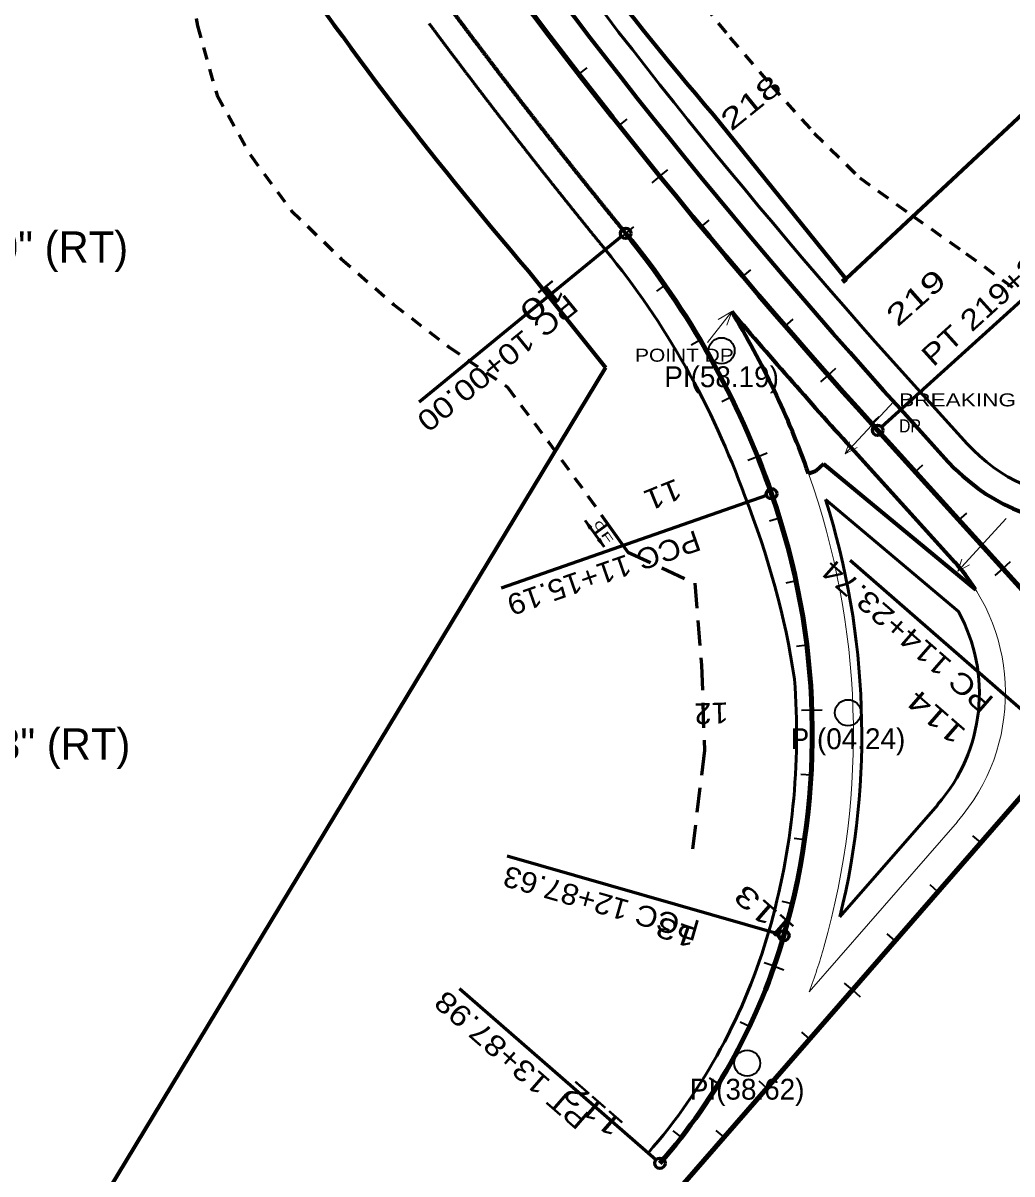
# Model space of a CAD drawing. Extents: x 2717836 to 2719883, y 337327 to 339813.
# Drawn here: x 2718674.4 to 2719054.1, y 337871.3 to 338313.3 of the extents above; entities that cross this region are included whole.
import ezdxf
from ezdxf.enums import TextEntityAlignment as Align

# ---------------------------------------------------------------- set-up
doc = ezdxf.new("R2010")
doc.units = 0
doc.header["$LTSCALE"] = 3.2
for name, pattern in [('LONG_DASHED', [7.5, 6, -1.5]), ('MEDIUM_DASHED', [4.5, 3, -1.5]), ('SHORT_DASHED', [2.7, 1.5, -1.2])]:
    doc.linetypes.add(name, pattern=pattern)
for name, color, linetype, lineweight in [('1', 7, 'Continuous', 106), ('2', 7, 'Continuous', 13), ('22', 7, 'SHORT_DASHED', 60), ('23', 7, 'Continuous', 70), ('3', 7, 'Continuous', 70), ('31', 7, 'Continuous', 35), ('52', 7, 'Continuous', 53), ('6', 7, 'Continuous', 53), ('60', 7, 'Continuous', 13), ('61', 7, 'Continuous', 13), ('62', 7, 'Continuous', 13), ('8', 7, 'Continuous', 70)]:
    doc.layers.add(name, color=color, linetype=linetype, lineweight=lineweight)

msp = doc.modelspace()

# ---------------------------------------------------------------- hatches: boundary and pattern name
at = {"layer": '23'}
msp.add_hatch(color=256, dxfattribs=at).paths.add_polyline_path([(2718989.701, 338213.433), (2718988.659, 338214.512), (2718989.738, 338215.554), (2718990.78, 338214.474)])
at = {"layer": '52'}
for points in [[(2718890.257, 338122.283), (2718892.832, 338119.693), (2718891.815, 338120.076), (2718891.826, 338118.982)], [(2718897.478, 338112.08), (2718894.903, 338114.67), (2718895.92, 338114.288), (2718895.908, 338115.382)]]:
    msp.add_hatch(color=256, dxfattribs=at).paths.add_polyline_path(points)

# ---------------------------------------------------------------- linework, layer by layer
at = {"layer": '1'}
for p, q in [((2719002.473, 338156.897), (2719189.327, 337950.539)), ((2718598.813, 337489.479), (2719074.059, 338035.314))]:
    msp.add_line(p, q, dxfattribs=at)
for centre, radius, start, end in [((2720744.453, 339734.238), 2350, 206.79977, 222.16044), ((2718650.191, 338023.775), 330, 19.23982, 39.23982), ((2718697.399, 338040.251), 280, 343.95467, 19.23982), ((2718745.451, 338026.431), 230, 318.95467, 343.95467)]:
    msp.add_arc(centre, radius, start, end, dxfattribs=at)
at = {"layer": '2'}
msp.add_line((2719033.086, 338006.53), (2718976.223, 337941.221), dxfattribs=at)
for centre, radius, start, end in [((2718692.921, 338040.106), 300.266, 344.21749, 19.50264), ((2718976.549, 338055.909), 75, 318.86607, 42.16044), ((2718745.451, 338026.431), 246, 339.73408, 343.95467)]:
    msp.add_arc(centre, radius, start, end, dxfattribs=at)
at = {"layer": '22'}
for p, q in [((2718736.378, 338340.568), (2718741.398, 338312.243)), ((2718930.49, 338326.699), (2718945.807, 338307.673)), ((2718741.398, 338312.243), (2718748.912, 338285.405)), ((2718945.807, 338307.673), (2718961.775, 338289.179)), ((2718961.775, 338289.179), (2718978.102, 338271.004)), ((2718748.912, 338285.405), (2718761.889, 338262.366)), ((2718978.102, 338271.004), (2718995.614, 338253.858)), ((2718761.889, 338262.366), (2718777.485, 338241.226)), ((2718995.614, 338253.858), (2719015.923, 338239.196)), ((2718777.485, 338241.226), (2718796.55, 338222.768)), ((2718796.55, 338222.768), (2718816.646, 338205.231)), ((2718816.646, 338205.231), (2718837.975, 338188.825)), ((2718837.975, 338188.825), (2718860.375, 338173.479)), ((2718860.375, 338173.479), (2718875.971, 338152.581)), ((2718875.971, 338152.581), (2718891.404, 338131.497)), ((2718891.404, 338131.497), (2718898.972, 338120.794))]:
    msp.add_line(p, q, dxfattribs=at)
at = {"layer": '22', "linetype": 'LONG_DASHED'}
msp.add_line((2718898.972, 338120.794), (2718906.541, 338110.092), dxfattribs=at)
at = {"layer": '22', "linetype": 'MEDIUM_DASHED'}
msp.add_line((2718906.541, 338110.092), (2718932.305, 338098.2), dxfattribs=at)
at = {"layer": '22'}
msp.add_lwpolyline([(2719015.923, 338239.196), (2719036.374, 338224.824), (2719056.377, 338210.214)], dxfattribs=at)
at = {"layer": '22', "linetype": 'MEDIUM_DASHED'}
msp.add_lwpolyline([(2718932.305, 338098.2), (2718934.904, 338066.645), (2718935.99, 338033.903), (2718931.4, 337996.021)], dxfattribs=at)
at = {"layer": '23'}
for p, q in [((2719374.169, 338574.501), (2718990.259, 338215.014)), ((2718939.297, 338278.13), (2718990.259, 338215.014)), ((2718868.503, 338217.98), (2718898.006, 338180.983)), ((2718898.006, 338180.983), (2718492.996, 337510.896))]:
    msp.add_line(p, q, dxfattribs=at)
at = {"layer": '23', "lineweight": 25}
msp.add_lwpolyline([(2718989.701, 338213.433), (2718988.659, 338214.512), (2718989.738, 338215.554), (2718990.78, 338214.474)], close=True, dxfattribs=at)
at = {"layer": '23'}
for centre, radius, start, end in [((2718932.366, 337992.345), 585.751, 113.27176, 113.27176), ((2720030.046, 339206.574), 1432.39, 206.96023, 220.40436), ((2719954.557, 339151.911), 1432.39, 206.65897, 220.69325)]:
    msp.add_arc(centre, radius, start, end, dxfattribs=at)
at = {"layer": '3'}
for p, q in [((2719011.368, 338164.951), (2719029.47, 338144.96)), ((2718975.96, 338140.349), (2718978.769, 338141.359)), ((2718981.734, 338144.044), (2718978.769, 338141.359))]:
    msp.add_line(p, q, dxfattribs=at)
at = {"layer": '3', "lineweight": 13}
msp.add_lwpolyline([(2718993.577, 338148.842), (2719031.255, 338107.232), (2719032.145, 338106.25)], dxfattribs=at)
at = {"layer": '3'}
msp.add_lwpolyline([(2718981.734, 338144.044), (2719039.155, 338096.513), (2719040.109, 338095.724)], dxfattribs=at)
for centre, radius, start, end in [((2720744.453, 339734.238), 2338, 206.79977, 222.16044), ((2718650.191, 338023.775), 330, 19.23982, 39.23982), ((2718650.191, 338023.775), 330, 19.23982, 39.23982), ((2719085.065, 338195.301), 75, 222.16044, 316.72468), ((2718697.399, 338040.251), 280, 343.95467, 19.23982), ((2718697.399, 338040.251), 280, 343.95467, 19.23982), ((2718745.451, 338026.431), 230, 318.95467, 343.95467), ((2718745.451, 338026.431), 230, 318.95467, 343.95467)]:
    msp.add_arc(centre, radius, start, end, dxfattribs=at)
at = {"layer": '3', "lineweight": 13}
for centre, radius, start, end in [((2718662.067, 338029.421), 332.917, 19.82595, 31.31675), ((2720759.569, 339747.514), 2382.117, 220.43651, 222.14825), ((2721152.646, 340103.725), 2912.583, 222.15462, 222.1586), ((2718640.384, 338021.681), 355.94, 19.4749, 19.81422)]:
    msp.add_arc(centre, radius, start, end, dxfattribs=at)
at = {"layer": '3'}
for points in [[(2718838.33, 338319.116), (2718838.769, 338318.524), (2718839.215, 338317.924), (2718839.655, 338317.332), (2718840.102, 338316.732), (2718840.542, 338316.141), (2718840.989, 338315.541), (2718841.429, 338314.95), (2718841.87, 338314.359), (2718842.318, 338313.76), (2718842.759, 338313.169), (2718843.207, 338312.57), (2718843.648, 338311.98), (2718844.09, 338311.39), (2718844.538, 338310.791), (2718844.981, 338310.201), (2718845.429, 338309.603), (2718845.872, 338309.013), (2718846.321, 338308.415), (2718846.764, 338307.826), (2718847.207, 338307.236), (2718847.656, 338306.639), (2718848.1, 338306.05), (2718848.55, 338305.453), (2718848.994, 338304.864), (2718849.438, 338304.275), (2718849.888, 338303.679), (2718850.333, 338303.09), (2718850.783, 338302.494), (2718851.228, 338301.906), (2718851.679, 338301.309), (2718852.124, 338300.722), (2718852.57, 338300.134), (2718853.022, 338299.538), (2718853.467, 338298.951), (2718853.919, 338298.355), (2718854.365, 338297.768), (2718854.818, 338297.173), (2718855.264, 338296.586), (2718855.711, 338295.999), (2718856.164, 338295.405), (2718856.611, 338294.818), (2718857.064, 338294.224), (2718857.512, 338293.637), (2718857.96, 338293.051), (2718858.413, 338292.457), (2718858.861, 338291.872), (2718859.316, 338291.278), (2718859.764, 338290.692), (2718860.219, 338290.099), (2718860.667, 338289.514), (2718861.116, 338288.929), (2718861.571, 338288.336), (2718862.021, 338287.751), (2718862.476, 338287.158), (2718862.926, 338286.574), (2718863.376, 338285.989), (2718863.832, 338285.397), (2718864.282, 338284.813), (2718864.738, 338284.221), (2718865.189, 338283.637), (2718865.646, 338283.045), (2718866.097, 338282.462), (2718866.548, 338281.878), (2718867.005, 338281.287), (2718867.457, 338280.704), (2718867.914, 338280.113), (2718868.366, 338279.53), (2718868.818, 338278.947), (2718869.277, 338278.357), (2718869.729, 338277.774), (2718870.188, 338277.184), (2718870.64, 338276.602), (2718871.099, 338276.012), (2718871.553, 338275.43)], [(2718871.553, 338275.43), (2718872.006, 338274.848), (2718872.465, 338274.259), (2718872.919, 338273.677), (2718873.379, 338273.088), (2718873.833, 338272.507), (2718874.293, 338271.918), (2718874.748, 338271.337), (2718875.202, 338270.756), (2718875.663, 338270.168), (2718876.118, 338269.587), (2718876.579, 338268.999), (2718877.035, 338268.419), (2718877.49, 338267.839), (2718877.952, 338267.251), (2718878.408, 338266.671), (2718878.87, 338266.084), (2718879.326, 338265.504), (2718879.789, 338264.917), (2718880.245, 338264.338), (2718880.702, 338263.759), (2718881.165, 338263.172), (2718881.622, 338262.593), (2718882.086, 338262.007), (2718882.543, 338261.428), (2718883.001, 338260.85), (2718883.465, 338260.264), (2718883.923, 338259.686), (2718884.387, 338259.1), (2718884.845, 338258.522), (2718885.31, 338257.937), (2718885.769, 338257.36), (2718886.228, 338256.782), (2718886.693, 338256.197), (2718887.152, 338255.62), (2718887.618, 338255.035), (2718888.078, 338254.459), (2718888.537, 338253.882), (2718889.004, 338253.298), (2718889.464, 338252.721), (2718889.93, 338252.137), (2718890.391, 338251.561), (2718890.858, 338250.978), (2718891.319, 338250.402), (2718891.78, 338249.826), (2718892.247, 338249.243), (2718892.709, 338248.668), (2718893.176, 338248.085), (2718893.638, 338247.51), (2718894.106, 338246.927), (2718894.569, 338246.352), (2718895.031, 338245.778), (2718895.5, 338245.195), (2718895.962, 338244.621), (2718896.431, 338244.039), (2718896.894, 338243.465), (2718897.358, 338242.891), (2718897.827, 338242.31), (2718898.291, 338241.736), (2718898.761, 338241.155), (2718899.225, 338240.581), (2718899.695, 338240), (2718900.16, 338239.427), (2718900.624, 338238.855), (2718901.095, 338238.274), (2718901.56, 338237.702), (2718902.031, 338237.121), (2718902.496, 338236.549), (2718902.962, 338235.977), (2718903.433, 338235.397), (2718903.899, 338234.825), (2718904.371, 338234.246), (2718904.837, 338233.674), (2718905.776, 338232.524)]]:
    msp.add_spline(points, degree=3, dxfattribs=at)
at = {"layer": '31'}
for p, q in [((2718887.829, 338293.596), (2718890.989, 338296.049)), ((2718903.26, 338273.927), (2718906.394, 338276.413)), ((2718918.899, 338254.423), (2718922.006, 338256.942)), ((2718918.899, 338254.423), (2718915.792, 338251.904)), ((2718905.778, 338232.522), (2718908.876, 338235.052)), ((2718934.745, 338235.086), (2718937.825, 338237.638)), ((2718905.778, 338232.522), (2718902.68, 338229.992)), ((2718950.795, 338215.919), (2718953.848, 338218.503)), ((2718920.844, 338212.579), (2718917.563, 338210.291)), ((2718967.049, 338196.924), (2718970.074, 338199.541)), ((2718934.357, 338191.553), (2718930.913, 338189.52)), ((2718983.503, 338178.103), (2718986.501, 338180.751)), ((2718983.503, 338178.103), (2718980.506, 338175.454)), ((2718946.241, 338169.565), (2718942.652, 338167.798)), ((2719000.157, 338159.458), (2719003.126, 338162.138)), ((2718956.426, 338146.74), (2718952.714, 338145.25)), ((2718956.426, 338146.74), (2718960.137, 338148.231)), ((2719016.936, 338140.924), (2719019.901, 338143.609)), ((2718964.829, 338123.202), (2718961.009, 338122.017)), ((2719033.716, 338122.392), (2719036.681, 338125.077)), ((2719050.496, 338103.861), (2719053.461, 338106.546)), ((2719050.496, 338103.861), (2719047.531, 338101.176)), ((2718971.16, 338099.026), (2718967.249, 338098.186)), ((2718975.311, 338074.381), (2718971.34, 338073.893)), ((2718977.247, 338049.464), (2718973.249, 338049.333)), ((2718977.247, 338049.464), (2718981.245, 338049.596)), ((2718976.954, 338024.474), (2718972.96, 338024.7)), ((2718974.433, 337999.61), (2718970.476, 338000.191)), ((2719042.056, 337998.557), (2719039.039, 338001.184)), ((2719025.639, 337979.703), (2719022.623, 337982.329)), ((2718969.706, 337975.07), (2718965.816, 337976.001)), ((2719009.223, 337960.848), (2719006.206, 337963.475)), ((2718962.753, 337951.067), (2718958.974, 337952.377)), ((2718962.753, 337951.067), (2718966.532, 337949.756)), ((2718992.807, 337941.993), (2718989.79, 337944.62)), ((2718992.807, 337941.993), (2718995.823, 337939.367)), ((2718953.295, 337927.938), (2718949.68, 337929.651)), ((2718976.39, 337923.138), (2718973.373, 337925.765)), ((2718941.384, 337905.972), (2718937.976, 337908.067)), ((2718959.974, 337904.284), (2718956.957, 337906.91)), ((2718927.16, 337885.428), (2718923.999, 337887.88)), ((2718943.557, 337885.429), (2718940.541, 337888.056))]:
    msp.add_line(p, q, dxfattribs=at)
at = {"layer": '31', "lineweight": 60}
for p, q in [((2718904.229, 338231.257), (2718826.462, 338167.741)), ((2719003.955, 338158.239), (2719083.848, 338230.581)), ((2718959.872, 338131.858), (2718857.934, 338096.28)), ((2719072.55, 338036.627), (2718991.882, 338106.863)), ((2718964.569, 337963.412), (2718860.262, 337993.411)), ((2718917.406, 337876.713), (2718842.011, 337942.358))]:
    msp.add_line(p, q, dxfattribs=at)
for centre in [(2718905.778, 338232.522), (2719002.473, 338156.897), (2718961.76, 338132.517), (2718966.491, 337962.86), (2718918.914, 337875.4)]:
    msp.add_circle(centre, 2, dxfattribs=at)
at = {"layer": '31'}
for centre in [(2718942.586, 338187.455), (2718991.104, 338048.441), (2718952.397, 337913.856)]:
    msp.add_circle(centre, 5, dxfattribs=at)
at = {"layer": '52'}
for p, q in [((2718890.257, 338122.283), (2718897.478, 338112.08)), ((2718893.867, 338117.182), (2718898.972, 338120.794))]:
    msp.add_line(p, q, dxfattribs=at)
at = {"layer": '52', "lineweight": 25}
for points in [[(2718890.257, 338122.283), (2718892.832, 338119.693), (2718891.815, 338120.076), (2718891.826, 338118.982)], [(2718897.478, 338112.08), (2718894.903, 338114.67), (2718895.92, 338114.288), (2718895.908, 338115.382)]]:
    msp.add_lwpolyline(points, close=True, dxfattribs=at)
at = {"layer": '6'}
for p, q in [((2719018.781, 338171.663), (2719036.882, 338151.672)), ((2718982.514, 338130.307), (2719033.495, 338087.249)), ((2718988.031, 337970.012), (2719025.544, 338013.097))]:
    msp.add_line(p, q, dxfattribs=at)
for centre, radius, start, end in [((2720744.453, 339734.238), 2328, 208.64257, 222.16044), ((2718650.191, 338023.775), 320, 19.68984, 39.23982), ((2719085.065, 338195.301), 65, 222.16044, 316.72468), ((2718654.256, 338013.029), 320, 8.68814, 21.747), ((2718697.399, 338040.251), 299, 346.41349, 17.52915), ((2718976.549, 338055.909), 65, 318.86607, 28.82624), ((2718697.399, 338040.251), 274, 343.95467, 4.41993), ((2718745.451, 338026.431), 224, 318.95467, 343.95467)]:
    msp.add_arc(centre, radius, start, end, dxfattribs=at)
for points in [[(2718830.301, 338313.154), (2718830.742, 338312.56), (2718831.19, 338311.958), (2718831.632, 338311.364), (2718832.08, 338310.761), (2718832.522, 338310.167), (2718832.971, 338309.565), (2718833.413, 338308.972), (2718833.856, 338308.378), (2718834.305, 338307.777), (2718834.748, 338307.183), (2718835.198, 338306.582), (2718835.641, 338305.989), (2718836.085, 338305.396), (2718836.535, 338304.795), (2718836.979, 338304.203), (2718837.43, 338303.602), (2718837.874, 338303.01), (2718838.325, 338302.409), (2718838.77, 338301.817), (2718839.215, 338301.225), (2718839.666, 338300.626), (2718840.112, 338300.034), (2718840.564, 338299.434), (2718841.009, 338298.843), (2718841.455, 338298.252), (2718841.908, 338297.653), (2718842.354, 338297.062), (2718842.807, 338296.463), (2718843.253, 338295.872), (2718843.706, 338295.274), (2718844.153, 338294.683), (2718844.601, 338294.093), (2718845.054, 338293.495), (2718845.502, 338292.905), (2718845.956, 338292.307), (2718846.404, 338291.717), (2718846.858, 338291.12), (2718847.307, 338290.53), (2718847.755, 338289.941), (2718848.21, 338289.344), (2718848.659, 338288.755), (2718849.114, 338288.158), (2718849.564, 338287.569), (2718850.013, 338286.981), (2718850.469, 338286.384), (2718850.919, 338285.796), (2718851.375, 338285.2), (2718851.825, 338284.612), (2718852.282, 338284.016), (2718852.732, 338283.428), (2718853.183, 338282.84), (2718853.64, 338282.245), (2718854.091, 338281.658), (2718854.549, 338281.063), (2718855, 338280.476), (2718855.452, 338279.889), (2718855.91, 338279.294), (2718856.362, 338278.707), (2718856.821, 338278.113), (2718857.273, 338277.527), (2718857.732, 338276.932), (2718858.185, 338276.346), (2718858.638, 338275.76), (2718859.097, 338275.167), (2718859.55, 338274.581), (2718860.01, 338273.988), (2718860.464, 338273.402), (2718860.918, 338272.817), (2718861.378, 338272.224), (2718861.832, 338271.639), (2718862.293, 338271.046), (2718862.747, 338270.462), (2718863.208, 338269.869), (2718863.662, 338269.286)], [(2718863.664, 338269.284), (2718864.119, 338268.701), (2718864.58, 338268.109), (2718865.036, 338267.525), (2718865.498, 338266.933), (2718865.953, 338266.35), (2718866.416, 338265.758), (2718866.872, 338265.175), (2718867.328, 338264.592), (2718867.791, 338264.001), (2718868.248, 338263.418), (2718868.711, 338262.827), (2718869.169, 338262.244), (2718869.626, 338261.662), (2718870.09, 338261.072), (2718870.547, 338260.49), (2718871.012, 338259.9), (2718871.47, 338259.318), (2718871.934, 338258.728), (2718872.393, 338258.146), (2718872.851, 338257.565), (2718873.316, 338256.976), (2718873.775, 338256.394), (2718874.241, 338255.805), (2718874.7, 338255.224), (2718875.16, 338254.644), (2718875.626, 338254.055), (2718876.086, 338253.475), (2718876.552, 338252.886), (2718877.012, 338252.306), (2718877.479, 338251.718), (2718877.94, 338251.138), (2718878.4, 338250.559), (2718878.868, 338249.971), (2718879.329, 338249.392), (2718879.796, 338248.804), (2718880.258, 338248.225), (2718880.72, 338247.646), (2718881.188, 338247.059), (2718881.65, 338246.481), (2718882.119, 338245.894), (2718882.581, 338245.316), (2718883.05, 338244.73), (2718883.513, 338244.151), (2718883.976, 338243.573), (2718884.445, 338242.988), (2718884.909, 338242.41), (2718885.378, 338241.824), (2718885.842, 338241.247), (2718886.312, 338240.662), (2718886.776, 338240.085), (2718887.241, 338239.508), (2718887.711, 338238.923), (2718888.176, 338238.346), (2718888.647, 338237.762), (2718889.112, 338237.185), (2718889.577, 338236.609), (2718890.049, 338236.025), (2718890.514, 338235.449), (2718890.986, 338234.865), (2718891.452, 338234.29), (2718891.925, 338233.706), (2718892.391, 338233.131), (2718892.857, 338232.556), (2718893.33, 338231.973), (2718893.797, 338231.398), (2718894.27, 338230.815), (2718894.737, 338230.24), (2718895.205, 338229.666), (2718895.679, 338229.084), (2718896.146, 338228.509), (2718896.62, 338227.927), (2718897.089, 338227.353), (2718898.029, 338226.201)]]:
    msp.add_spline(points, degree=3, dxfattribs=at)
at = {"layer": '60'}
msp.add_line((2719033.232, 338102.845), (2719034.862, 338107.376), dxfattribs=at)
msp.add_lwpolyline([(2719051.887, 338122.962), (2719033.232, 338102.845), (2719037.76, 338105.201)], dxfattribs=at)
at = {"layer": '61'}
msp.add_line((2718990.042, 338147.876), (2718994.569, 338150.232), dxfattribs=at)
msp.add_lwpolyline([(2719008.697, 338167.993), (2718990.042, 338147.876), (2718991.672, 338152.407)], dxfattribs=at)
at = {"layer": '62'}
for p in [(2718937.158, 338190.612), (2718941.324, 338199.492), (2718944.584, 338197.317)]:
    msp.add_line(p, (2718946.477, 338202.464), dxfattribs=at)
at = {"layer": '8'}
for p, q in [((2718993.575, 338148.843), (2719032.142, 338106.25)), ((2718975.957, 338140.35), (2718978.767, 338141.36)), ((2718981.732, 338144.045), (2718978.767, 338141.36)), ((2718981.732, 338144.045), (2719040.053, 338095.769))]:
    msp.add_line(p, q, dxfattribs=at)
for centre, radius, start, end in [((2720744.451, 339734.239), 2362, 220.42917, 222.16044), ((2718650.189, 338023.776), 346, 19.68926, 31.09375), ((2718976.547, 338055.91), 75, 32.50196, 42.16044)]:
    msp.add_arc(centre, radius, start, end, dxfattribs=at)

# ---------------------------------------------------------------- texts
at = {"layer": '31'}
for s, rotation, width, p in [('218', 39.029, 1.45, (2718946.276, 338271.466)), ('PT 219+28.45', 42.16, 1.2, (2719023.844, 338180.97)), ('219', 41.467, 1.45, (2719010.131, 338196.295)), ('10', 219.24, 1.55, (2718878.463, 338215.378)), ('PC 10+00.00', 219.24, 1.2, (2718883.208, 338209.569)), ('11', 201.877, 1.2, (2718925.24, 338138.528)), ('PCC 11+15.19', 199.24, 1.1, (2718932.701, 338118.668)), ('PC 114+23.74', 138.955, 1.2, (2719047.626, 338053.687)), ('114', 138.955, 1.4, (2719036.965, 338041.442)), ('12', 181.886, 1.1, (2718945.133, 338052.409)), ('PCC 12+87.63', 163.955, 1.1, (2718934.77, 337968.341)), ('113', 138.955, 1.45, (2718971.299, 337966.023)), ('13', 160.873, 1.3, (2718933.83, 337965.331)), ('PT 13+87.98', 138.955, 1.2, (2718892.482, 337893.773)), ('112', 138.955, 1.45, (2718905.634, 337890.604))]:
    msp.add_text(s, height=8, rotation=rotation, dxfattribs=dict(at, width=width)).set_placement(p)
for s, p in [('DELTA = 20° 00\' 00.00" (RT)', (2718508.303, 338221.273)), ('DELTA = 35° 17\' 06.53" (RT)', (2718509.144, 338030.42))]:
    msp.add_text(s, height=12, dxfattribs=at).set_placement(p)
for s, p in [('PI(58.19)', (2718942.587, 338173.455)), ('PI(04.24)', (2718991.104, 338034.441)), ('PI(38.62)', (2718952.397, 337899.856))]:
    msp.add_text(s, height=8, dxfattribs=at).set_placement(p, align=Align.CENTER)
at = {"layer": '52'}
for s, width, p in [('C', 1.45, (2718894.506, 338119.281)), ('F', 1.95, (2718897.451, 338114.924))]:
    msp.add_text(s, height=3, rotation=305.287, dxfattribs=dict(at, width=width)).set_placement(p, align=Align.CENTER)
at = {"layer": '61'}
for s, width, p in [('BREAKING LINE ', 1.3, (2719010.723, 338166.075)), ('DP', 0.9, (2719010.723, 338156.076))]:
    msp.add_text(s, height=5, dxfattribs=dict(at, width=width)).set_placement(p)
at = {"layer": '62', "width": 1.2}
msp.add_text('POINT DP', height=5, dxfattribs=at).set_placement((2718909.37, 338183.235))

doc.saveas('drawing.dxf')
